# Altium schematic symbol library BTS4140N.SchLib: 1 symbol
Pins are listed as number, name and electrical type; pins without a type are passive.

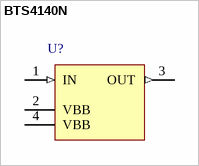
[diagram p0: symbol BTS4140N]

## BTS4140N
designator U?
Smart High-Side Power Switch, 1 Channel, 0.9 A Load Current, -40 to 150 degC, PG-SOT-223, Tube, Green; Manufacturer: Infineon; PartNumber: BTS4140N; Channels: 1; Green: TRUE; Group: Automotive Qualified; Load Current (typ): 0.9 A; Ptot (max): 1.7 W; Recommended Operating Voltage Max.: 60 V; Recommended Operating Voltage Min.: 4.9 V; RON @ 25degreesC: 1000 mOhm; RON(max) @ 150degreesC: 3000 mOhm; toff (max): 140 us; ton (max): 100 us
footprint INF-PG-SOT-223_N (SOT223, 4-Leads, Body 6.5x3.5mm, Pitch 2.3mm, IPC Medium Density)
footprint INF-PG-SOT-223_L (SOT223, 4-Leads, Body 6.5x3.5mm, Pitch 2.3mm, IPC High Density)
footprint INF-PG-SOT-223_M (SOT223, 4-Leads, Body 6.5x3.5mm, Pitch 2.3mm, IPC Low Density)
pins: 1 IN (in) "Input, activates the power switch in case of connection to GND", 2 VBB (power) "Positive power supply voltage", 3 OUT (out) "Output to the load", 4 VBB (power) "Positive power suppy voltage"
